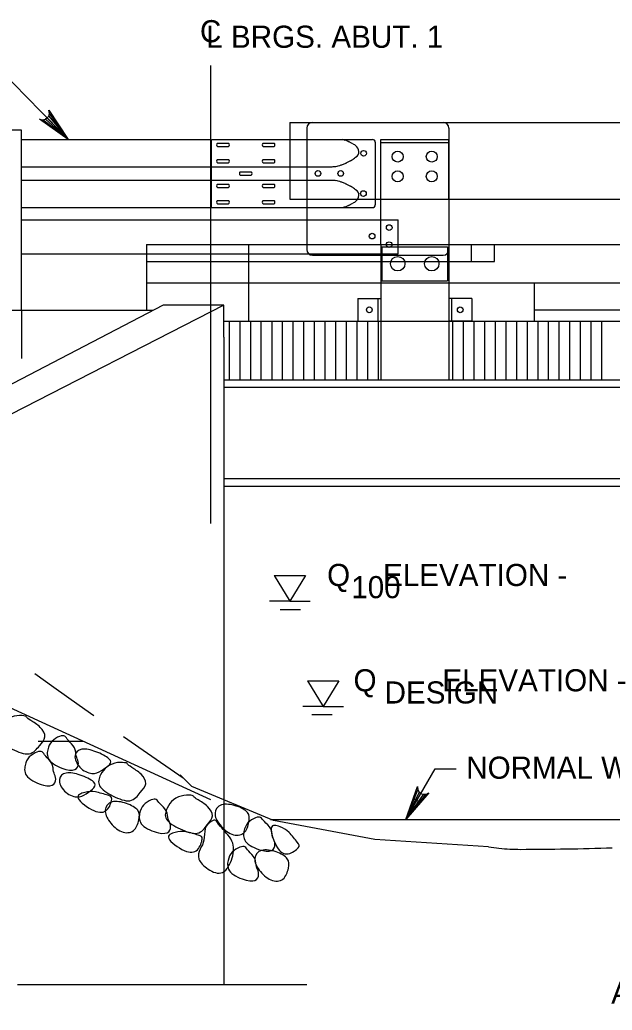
# Model space of a CAD drawing. Extents: x 638175 to 640495, y 294277 to 298435.
# Drawn here: x 638542.2 to 638622.4, y 297987.9 to 298122.2 of the extents above; entities that cross this region are included whole.
import ezdxf

# ---------------------------------------------------------------- set-up
doc = ezdxf.new("R2010")
doc.units = 0
for name, color, linetype in [('2', 7, 'Continuous'), ('3', 7, 'Continuous'), ('4', 7, 'Continuous'), ('5', 7, 'Continuous'), ('8', 7, 'Continuous'), ('Level 25', 7, 'Continuous')]:
    doc.layers.add(name, color=color, linetype=linetype)

msp = doc.modelspace()

# ---------------------------------------------------------------- linework, layer by layer
at = {"layer": '2'}
for p, q in [((638578.73, 298108.3), (638578.73, 298105.99)), ((638578.73, 298108.3), (638751.73, 298108.3)), ((638542.4, 298106), (638568.08, 298106)), ((638568.08, 298106), (638568.08, 298096.76)), ((638568.15, 298106), (638578.73, 298106)), ((638578.73, 298106), (638589.95, 298106)), ((638578.73, 298105.99), (638578.73, 298097.91)), ((638591.05, 298105.99), (638600.28, 298105.99)), ((638591.05, 298091.74), (638591.05, 298105.99)), ((638600.28, 298097.91), (638600.28, 298105.99)), ((638568.95, 298105.49), (638570.43, 298105.49)), ((638568.95, 298105.03), (638570.43, 298105.03)), ((638575.12, 298105.49), (638576.6, 298105.49)), ((638575.12, 298105.03), (638576.6, 298105.03)), ((638590.32, 298105.63), (638590.32, 298097.13)), ((638591.05, 298105.61), (638600.28, 298105.61)), ((638568.95, 298103.28), (638570.43, 298103.28)), ((638575.12, 298103.28), (638576.6, 298103.28)), ((638542.4, 298102.31), (638578.73, 298102.31)), ((638568.95, 298102.81), (638570.43, 298102.81)), ((638575.12, 298102.81), (638576.6, 298102.81)), ((638578.73, 298102.31), (638584.48, 298102.31)), ((638572.03, 298101.61), (638573.51, 298101.61)), ((638572.03, 298101.15), (638573.51, 298101.15)), ((638542.4, 298100.46), (638578.73, 298100.46)), ((638568.95, 298099.95), (638570.43, 298099.95)), ((638568.95, 298099.49), (638570.43, 298099.49)), ((638575.12, 298099.95), (638576.6, 298099.95)), ((638575.12, 298099.49), (638576.6, 298099.49)), ((638578.73, 298100.46), (638584.48, 298100.46)), ((638578.73, 298097.91), (638581.04, 298097.91)), ((638581.04, 298097.91), (638591.05, 298097.91)), ((638591.05, 298097.91), (638600.28, 298097.91)), ((638600.28, 298097.91), (638600.28, 298091.74)), ((638600.28, 298097.91), (638638.71, 298097.91)), ((638542.4, 298096.76), (638581.04, 298096.76)), ((638568.95, 298097.73), (638570.43, 298097.73)), ((638568.95, 298097.27), (638570.43, 298097.27)), ((638575.12, 298097.73), (638576.6, 298097.73)), ((638575.12, 298097.27), (638576.6, 298097.27)), ((638581.04, 298096.76), (638589.95, 298096.76)), ((638542.4, 298095.1), (638581.04, 298095.1)), ((638581.04, 298095.1), (638593.4, 298095.1)), ((638593.4, 298090.48), (638593.4, 298095.1)), ((638559.3, 298091.74), (638591.05, 298091.74)), ((638559.3, 298091.74), (638559.3, 298082.8)), ((638573.15, 298091.74), (638573.15, 298081.36)), ((638581.04, 298091.74), (638581.04, 298091.08)), ((638591.05, 298091.74), (638591.05, 298073.42)), ((638591.05, 298091.74), (638600.28, 298091.74)), ((638591.21, 298091.46), (638591.21, 298086.85)), ((638591.21, 298091.46), (638600.09, 298091.46)), ((638600.09, 298091.46), (638600.09, 298086.85)), ((638600.28, 298091.74), (638600.28, 298073.42)), ((638600.28, 298091.74), (638638.71, 298091.74)), ((638603.36, 298089.44), (638603.36, 298091.74)), ((638606.45, 298089.44), (638606.45, 298091.74)), ((638542.4, 298090.48), (638559.3, 298090.48)), ((638559.3, 298090.48), (638593.4, 298090.48)), ((638559.3, 298089.44), (638606.45, 298089.44)), ((638559.3, 298086.55), (638591.05, 298086.55)), ((638591.05, 298086.55), (638600.28, 298086.55)), ((638591.21, 298086.85), (638600.09, 298086.85)), ((638600.28, 298086.55), (638616.44, 298086.55)), ((638611.82, 298086.55), (638611.82, 298081.36)), ((638612.04, 298086.55), (638638.71, 298086.55)), ((638587.96, 298084.45), (638591.05, 298084.45)), ((638587.96, 298084.45), (638587.96, 298081.36)), ((638590.68, 298084.45), (638590.68, 298081.36)), ((638591.05, 298084.45), (638591.05, 298081.36)), ((638603.38, 298084.45), (638600.28, 298084.45)), ((638600.28, 298084.45), (638600.28, 298081.36)), ((638600.65, 298084.45), (638600.65, 298081.36)), ((638603.38, 298084.45), (638603.38, 298081.36)), ((638611.82, 298082.89), (638625.9, 298082.89)), ((638587.96, 298081.36), (638591.05, 298081.36)), ((638591.05, 298081.36), (638600.28, 298081.36)), ((638603.38, 298081.36), (638600.28, 298081.36)), ((638600.28, 298081.36), (638638.71, 298081.36))]:
    msp.add_line(p, q, dxfattribs=at)
for centre, radius in [((638588.74, 298104.12), 0.385), ((638593.36, 298103.68), 0.748), ((638597.97, 298103.68), 0.748), ((638582.55, 298101.39), 0.385), ((638585.63, 298101.39), 0.385), ((638593.36, 298100.99), 0.748), ((638597.97, 298100.99), 0.748), ((638588.71, 298098.67), 0.385), ((638592.2, 298094.05), 0.385), ((638589.89, 298092.89), 0.385), ((638592.2, 298091.74), 0.385), ((638593.36, 298089.15), 0.978), ((638597.97, 298089.15), 0.978), ((638589.51, 298082.9), 0.385), ((638601.82, 298082.9), 0.385)]:
    msp.add_circle(centre, radius, dxfattribs=at)
for centre, radius, start, end in [((638582.91, 298096.28), 10.17, 71.5066, 72.9766), ((638589.95, 298105.63), 0.369, 0, 90), ((638569.09, 298105.26), 0.269, 120.8559, 239.1441), ((638570.29, 298105.26), 0.269, 300.8559, 59.1441), ((638575.26, 298105.26), 0.269, 120.8559, 239.1441), ((638576.46, 298105.26), 0.269, 300.8559, 59.1441), ((638585.53, 298104.13), 1.88, 68.0907, 71.5066), ((638562.09, 298045.83), 64.73, 67.6851, 68.0907), ((638584.41, 298100.22), 5.93, 66.3453, 67.6851), ((638585.82, 298103.44), 2.42, 63.4251, 66.3453), ((638572.67, 298077.16), 31.8, 62.6202, 63.4251), ((638586.86, 298104.55), 0.955, 54.6771, 62.6202), ((638584.86, 298101.73), 4.42, 50.9849, 54.6771), ((638587.18, 298104.37), 0.916, 301.3851, 59.6468), ((638569.09, 298103.05), 0.269, 120.8559, 239.1441), ((638570.29, 298103.05), 0.269, 300.8559, 59.1441), ((638575.26, 298103.05), 0.269, 120.8559, 239.1441), ((638576.46, 298103.05), 0.269, 300.8559, 59.1441), ((638399.66, 298448.44), 392.83, 298.4725, 298.525), ((638586.74, 298104.25), 1.09, 298.525, 306.8818), ((638584.42, 298107.33), 4.94, 306.8818, 310.7993), ((638584.25, 298107.33), 5.03, 272.6429, 278.367), ((638584.67, 298104.49), 2.16, 278.367, 287.1115), ((638558.25, 298190.32), 91.96, 287.1115, 287.3611), ((638584.75, 298105.55), 3.14, 287.3611, 288.7111), ((638579.93, 298119.78), 18.18, 288.7111, 290.2329), ((638585.99, 298103.33), 0.644, 290.2329, 298.3215), ((638576.12, 298121.65), 21.45, 298.3215, 298.7501), ((638641.79, 298001.95), 115.08, 118.565, 118.7501), ((638647.18, 297992.04), 126.36, 118.4725, 118.565), ((638572.17, 298101.38), 0.269, 120.8559, 239.1441), ((638573.37, 298101.38), 0.269, 300.8559, 59.1441), ((638569.09, 298099.72), 0.269, 120.8559, 239.1441), ((638570.29, 298099.72), 0.269, 300.8559, 59.1441), ((638575.26, 298099.72), 0.269, 120.8559, 239.1441), ((638576.46, 298099.72), 0.269, 300.8559, 59.1441), ((638584.25, 298095.43), 5.03, 81.633, 87.3571), ((638584.67, 298098.28), 2.16, 72.8885, 81.633), ((638558.25, 298012.45), 91.96, 72.6389, 72.8885), ((638584.75, 298097.22), 3.14, 71.2889, 72.6389), ((638579.93, 298082.98), 18.18, 69.7671, 71.2889), ((638585.99, 298099.43), 0.644, 61.6785, 69.7671), ((638576.12, 298081.11), 21.45, 61.2499, 61.6785), ((638641.79, 298200.82), 115.08, 241.2499, 241.435), ((638647.18, 298210.72), 126.36, 241.435, 241.5275), ((638399.66, 297754.33), 392.83, 61.475, 61.5275), ((638586.74, 298098.52), 1.09, 53.1182, 61.475), ((638584.42, 298095.44), 4.94, 49.2007, 53.1182), ((638587.18, 298098.4), 0.916, 300.3532, 58.6149), ((638569.09, 298097.5), 0.269, 120.8559, 239.1441), ((638570.29, 298097.5), 0.269, 300.8559, 59.1441), ((638575.26, 298097.5), 0.269, 120.8559, 239.1441), ((638576.46, 298097.5), 0.269, 300.8559, 59.1441), ((638582.91, 298106.49), 10.17, 287.0234, 288.4934), ((638585.53, 298098.63), 1.88, 288.4934, 291.9093), ((638562.09, 298156.93), 64.73, 291.9093, 292.3149), ((638584.41, 298102.54), 5.93, 292.3149, 293.6547), ((638585.82, 298099.32), 2.42, 293.6547, 296.5749), ((638572.67, 298125.6), 31.8, 296.5749, 297.3798), ((638586.86, 298098.21), 0.955, 297.3798, 305.3229), ((638584.86, 298101.04), 4.42, 305.3229, 309.0151), ((638589.95, 298097.13), 0.369, 270, 0)]:
    msp.add_arc(centre, radius, start, end, dxfattribs=at)
at = {"layer": '3'}
for p, q in [((638542.4, 298107.27), (638538.07, 298107.27)), ((638542.4, 298082.8), (638542.4, 298107.27)), ((638561.58, 298083.52), (638496.45, 298049.64)), ((638569.79, 298083.52), (638503.58, 298049.64)), ((638569.79, 298083.52), (638503.58, 298049.64)), ((638569.79, 298083.52), (638561.58, 298083.52)), ((638569.79, 298083.52), (638561.58, 298083.52)), ((638569.79, 298079.19), (638569.79, 298083.52)), ((638569.79, 298079.19), (638569.79, 298083.52)), ((638560.19, 298082.8), (638486.79, 298082.8)), ((638560.19, 298082.8), (638495, 298082.8)), ((638542.4, 298082.8), (638542.4, 298076.31)), ((638569.79, 298081.36), (638591.05, 298081.36)), ((638569.79, 298079.19), (638569.79, 298016.47)), ((638569.79, 298073.43), (638748.57, 298073.43)), ((638569.79, 298073.43), (638748.57, 298073.43)), ((638569.79, 298073.42), (638748.57, 298073.42)), ((638569.79, 298072.43), (638748.57, 298072.43)), ((638569.79, 298060.01), (638748.57, 298060.01)), ((638569.79, 298059.01), (638748.57, 298059.01)), ((638526.61, 298035.47), (638567.99, 298016.49)), ((638544.63, 298024.41), (638550.73, 298024.41)), ((638569.79, 298016.47), (638569.79, 297991.42)), ((638576.14, 298013.81), (638736.87, 298013.81)), ((638541.85, 297991.42), (638581.05, 297991.42))]:
    msp.add_line(p, q, dxfattribs=at)
for centre, radius, start, end in [((638614.92, 298080.58), 71.1, 262.5202, 263.6598), ((638609.98, 298036.06), 26.31, 263.6598, 270.0618), ((638609.6, 298380.65), 370.9, 270.0618, 271.9788)]:
    msp.add_arc(centre, radius, start, end, dxfattribs=at)
for points in [[(638543.08, 298027.66), (638543.14, 298027.58), (638543.47, 298027.29), (638545.06, 298026.38), (638545.85, 298024.94), (638544.85, 298023.89), (638543.64, 298022.27), (638541.07, 298023.27), (638538.85, 298024.68), (638539.39, 298026.28), (638540.18, 298027.4), (638541.79, 298028.01), (638543.13, 298027.8), (638543.03, 298027.75), (638543.08, 298027.66)], [(638549.8, 298022.41), (638549.86, 298022.11), (638550.17, 298021.74), (638550.02, 298020.52), (638548.67, 298020.35), (638545.78, 298021.6), (638545.87, 298023.36), (638546.38, 298024.46), (638547.64, 298025.16), (638548.3, 298025.19), (638548.6, 298024.58), (638549.77, 298023.55), (638549.73, 298022.71), (638549.8, 298022.41)], [(638546.73, 298020.29), (638546.8, 298019.99), (638547.1, 298019.62), (638546.95, 298018.4), (638545.6, 298018.23), (638542.71, 298019.48), (638542.8, 298021.24), (638543.32, 298022.34), (638544.58, 298023.04), (638545.23, 298023.08), (638545.53, 298022.46), (638546.7, 298021.43), (638546.67, 298020.59), (638546.73, 298020.29)], [(638554.29, 298021.22), (638554.05, 298020.96), (638553.18, 298020.41), (638552.07, 298019.77), (638550.09, 298020.71), (638549.33, 298022.63), (638550.42, 298023.54), (638552.44, 298023.1), (638554.62, 298021.96), (638554.53, 298021.48), (638554.29, 298021.22)], [(638556.75, 298021.31), (638556.8, 298021.22), (638557.14, 298020.94), (638558.72, 298020.02), (638559.52, 298018.59), (638558.51, 298017.54), (638557.31, 298015.91), (638554.73, 298016.91), (638552.51, 298018.32), (638553.06, 298019.92), (638553.85, 298021.04), (638555.45, 298021.65), (638556.8, 298021.44), (638556.69, 298021.39), (638556.75, 298021.31)], [(638552.2, 298018.1), (638551.97, 298017.84), (638551.11, 298017.26), (638550.03, 298016.59), (638548.02, 298017.48), (638547.21, 298019.39), (638548.28, 298020.32), (638550.31, 298019.93), (638552.52, 298018.85), (638552.43, 298018.36), (638552.2, 298018.1)], [(638554.06, 298017.09), (638554.48, 298016.96), (638554.79, 298016.86), (638554.14, 298014.79), (638552.42, 298014.57), (638549.24, 298016.95), (638551.07, 298017.53), (638552.25, 298017.66), (638553.64, 298017.22), (638554.06, 298017.09)], [(638558.13, 298015.04), (638558.41, 298014.67), (638558.37, 298013.83), (638557.75, 298012.01), (638555.9, 298011.87), (638554.16, 298013.49), (638553.46, 298015.13), (638554.43, 298016.46), (638556.7, 298016.06), (638557.85, 298015.41), (638558.13, 298015.04)], [(638562.27, 298013.86), (638562.34, 298013.56), (638562.65, 298013.2), (638562.53, 298011.97), (638561.19, 298011.77), (638558.27, 298012.94), (638558.32, 298014.7), (638558.8, 298015.82), (638560.04, 298016.56), (638560.7, 298016.6), (638561.01, 298016), (638562.21, 298015), (638562.19, 298014.16), (638562.27, 298013.86)], [(638565.72, 298016.89), (638565.78, 298016.81), (638566.12, 298016.53), (638567.73, 298015.65), (638568.56, 298014.24), (638567.59, 298013.17), (638566.43, 298011.51), (638563.82, 298012.44), (638561.57, 298013.8), (638562.07, 298015.41), (638562.83, 298016.55), (638564.42, 298017.2), (638565.77, 298017.03), (638565.67, 298016.97), (638565.72, 298016.89)], [(638573.01, 298014.74), (638573.3, 298014.38), (638573.28, 298013.54), (638572.7, 298011.69), (638570.87, 298011.51), (638569.08, 298013.09), (638568.33, 298014.7), (638569.27, 298016.07), (638571.55, 298015.72), (638572.72, 298015.1), (638573.01, 298014.74)], [(638568.71, 298013.66), (638568.86, 298013.57), (638568.98, 298013.12), (638571.3, 298010.87), (638571.11, 298008.65), (638569.78, 298006.03), (638567.55, 298006.98), (638566.1, 298008.45), (638566.54, 298009.84), (638567.26, 298010.87), (638567.07, 298012.71), (638568.13, 298013.64), (638568.57, 298013.75), (638568.71, 298013.66)], [(638576.41, 298011.44), (638576.48, 298011.14), (638576.79, 298010.78), (638576.67, 298009.56), (638575.33, 298009.35), (638572.41, 298010.53), (638572.45, 298012.28), (638572.94, 298013.4), (638574.18, 298014.14), (638574.83, 298014.18), (638575.15, 298013.58), (638576.35, 298012.58), (638576.33, 298011.74), (638576.41, 298011.44)], [(638566.32, 298011.68), (638566.74, 298011.54), (638567.04, 298011.45), (638566.39, 298009.38), (638564.68, 298009.16), (638561.49, 298011.54), (638563.32, 298012.11), (638564.51, 298012.25), (638565.89, 298011.81), (638566.32, 298011.68)], [(638579.74, 298010.72), (638580.01, 298010.37), (638580.21, 298010.12), (638578.48, 298008.79), (638576.95, 298009.59), (638575.71, 298013.37), (638577.54, 298012.8), (638578.58, 298012.23), (638579.47, 298011.07), (638579.74, 298010.72)], [(638574.22, 298007.39), (638574.29, 298007.09), (638574.59, 298006.73), (638574.44, 298005.5), (638573.1, 298005.33), (638570.2, 298006.58), (638570.3, 298008.34), (638570.81, 298009.44), (638572.07, 298010.15), (638572.72, 298010.18), (638573.02, 298009.57), (638574.19, 298008.53), (638574.16, 298007.69), (638574.22, 298007.39)], [(638578.4, 298008.48), (638578.68, 298008.11), (638578.64, 298007.27), (638578.01, 298005.44), (638576.17, 298005.31), (638574.42, 298006.93), (638573.72, 298008.56), (638574.69, 298009.9), (638576.97, 298009.49), (638578.12, 298008.85), (638578.4, 298008.48)]]:
    msp.add_open_spline(points, degree=3, dxfattribs=at)
at = {"layer": '4'}
for p, q in [((638548.7, 298106), (638539.42, 298115.47)), ((638567.99, 298116.03), (638567.99, 298053.94)), ((638576.62, 298046.89), (638578.74, 298043.41)), ((638576.62, 298046.89), (638580.86, 298046.89)), ((638580.86, 298046.89), (638578.74, 298043.41)), ((638578.74, 298043.41), (638575.97, 298043.41)), ((638578.74, 298043.41), (638581.51, 298043.41)), ((638577.43, 298042.26), (638580.2, 298042.26)), ((638581.14, 298032.61), (638585.38, 298032.61)), ((638581.14, 298032.61), (638583.26, 298029.13)), ((638585.38, 298032.61), (638583.26, 298029.13)), ((638583.26, 298029.13), (638580.49, 298029.13)), ((638583.26, 298029.13), (638586.03, 298029.13)), ((638581.71, 298028.04), (638584.48, 298028.04)), ((638594.44, 298013.81), (638598.45, 298020.66)), ((638598.45, 298020.66), (638601.26, 298020.66))]:
    msp.add_line(p, q, dxfattribs=at)
for points in [[(638548.7, 298106), (638544.84, 298108.75), (638545.27, 298108.66), (638545.62, 298108.75), (638545.88, 298108.92), (638546.07, 298109.18), (638546.17, 298109.53), (638546.1, 298109.96), (638548.7, 298106), (638546.17, 298109.53), (638546.07, 298109.18), (638548.7, 298106), (638545.88, 298108.92), (638545.62, 298108.75), (638548.7, 298106), (638545.27, 298108.66)], [(638605.67, 298010.08), (638590.26, 298011.08), (638576.51, 298013.65), (638565.47, 298018.27), (638563.9, 298019.83)], [(638594.44, 298013.81), (638596.04, 298018.27), (638596.07, 298017.83), (638596.25, 298017.52), (638596.49, 298017.31), (638596.79, 298017.2), (638597.15, 298017.2), (638597.55, 298017.39), (638594.44, 298013.81), (638597.15, 298017.2), (638596.79, 298017.2), (638594.44, 298013.81), (638596.49, 298017.31), (638596.25, 298017.52), (638594.44, 298013.81), (638596.07, 298017.83)]]:
    msp.add_lwpolyline(points, dxfattribs=at)
msp.add_lwpolyline([(638595.55, 298016.65), (638596.38, 298016.16), (638594.5, 298013.92)], close=True, dxfattribs=at)
at = {"layer": '5'}
for p, q in [((638570.51, 298081.36), (638570.51, 298073.43)), ((638570.51, 298081.36), (638570.51, 298073.42)), ((638571.95, 298081.36), (638571.95, 298073.43)), ((638571.95, 298081.36), (638571.95, 298073.42)), ((638573.39, 298081.36), (638573.39, 298073.43)), ((638573.39, 298081.36), (638573.39, 298073.42)), ((638574.83, 298081.36), (638574.83, 298073.43)), ((638574.83, 298081.36), (638574.83, 298073.42)), ((638576.28, 298081.36), (638576.28, 298073.43)), ((638576.28, 298081.36), (638576.28, 298073.42)), ((638577.72, 298081.36), (638577.72, 298073.43)), ((638577.72, 298081.36), (638577.72, 298073.42)), ((638579.16, 298081.36), (638579.16, 298073.43)), ((638579.16, 298081.36), (638579.16, 298073.42)), ((638580.6, 298081.36), (638580.6, 298073.43)), ((638580.6, 298081.36), (638580.6, 298073.42)), ((638582.04, 298081.36), (638582.04, 298073.43)), ((638582.04, 298081.36), (638582.04, 298073.42)), ((638583.48, 298081.36), (638583.48, 298073.42)), ((638584.93, 298081.36), (638584.93, 298073.42)), ((638586.37, 298081.36), (638586.37, 298073.42)), ((638587.81, 298081.36), (638587.81, 298073.42)), ((638589.25, 298081.36), (638589.25, 298073.42)), ((638590.69, 298081.36), (638590.69, 298073.42)), ((638600.79, 298081.36), (638600.79, 298073.43)), ((638600.79, 298081.36), (638600.79, 298073.42)), ((638602.23, 298081.36), (638602.23, 298073.43)), ((638602.23, 298081.36), (638602.23, 298073.42)), ((638603.67, 298081.36), (638603.67, 298073.43)), ((638603.67, 298081.36), (638603.67, 298073.42)), ((638605.11, 298081.36), (638605.11, 298073.43)), ((638605.11, 298081.36), (638605.11, 298073.42)), ((638606.55, 298081.36), (638606.55, 298073.43)), ((638606.55, 298081.36), (638606.55, 298073.42)), ((638607.99, 298081.36), (638607.99, 298073.43)), ((638607.99, 298081.36), (638607.99, 298073.42)), ((638609.44, 298081.36), (638609.44, 298073.43)), ((638609.44, 298081.36), (638609.44, 298073.42)), ((638610.88, 298081.36), (638610.88, 298073.43)), ((638610.88, 298081.36), (638610.88, 298073.42)), ((638612.32, 298081.36), (638612.32, 298073.43)), ((638612.32, 298081.36), (638612.32, 298073.42)), ((638613.76, 298081.36), (638613.76, 298073.43)), ((638613.76, 298081.36), (638613.76, 298073.42)), ((638615.2, 298081.36), (638615.2, 298073.43)), ((638615.2, 298081.36), (638615.2, 298073.42)), ((638616.65, 298081.36), (638616.65, 298073.43)), ((638616.65, 298081.36), (638616.65, 298073.42)), ((638618.09, 298081.36), (638618.09, 298073.43)), ((638618.09, 298081.36), (638618.09, 298073.42)), ((638619.53, 298081.36), (638619.53, 298073.43)), ((638619.53, 298081.36), (638619.53, 298073.42)), ((638620.97, 298081.36), (638620.97, 298073.43)), ((638620.97, 298081.36), (638620.97, 298073.42))]:
    msp.add_line(p, q, dxfattribs=at)
at = {"layer": '8'}
for p, q in [((638546.77, 298031.69), (638544.17, 298033.54)), ((638550.19, 298029.25), (638546.77, 298031.69)), ((638552.19, 298027.84), (638550.19, 298029.25)), ((638558.86, 298023.17), (638556.22, 298025.01)), ((638564.31, 298019.42), (638558.86, 298023.17))]:
    msp.add_line(p, q, dxfattribs=at)
at = {"layer": 'Level 25'}
for p, q in [((638581.04, 298107.53), (638581.04, 298105.99)), ((638581.81, 298108.3), (638599.51, 298108.3)), ((638600.28, 298107.53), (638600.28, 298105.99)), ((638581.04, 298105.99), (638581.04, 298096.76)), ((638600.28, 298105.99), (638600.28, 298091.08)), ((638581.04, 298096.76), (638581.04, 298091.74)), ((638581.81, 298090.31), (638599.51, 298090.31))]:
    msp.add_line(p, q, dxfattribs=at)
for centre, start, end in [((638581.81, 298107.53), 90, 180), ((638599.51, 298107.53), 0, 90), ((638581.81, 298091.08), 180, 270), ((638599.51, 298091.08), 270, 0)]:
    msp.add_arc(centre, 0.77, start, end, dxfattribs=at)

# ---------------------------------------------------------------- texts
at = {"layer": '4'}
for s, p in [('C', (638566.56, 298119.18)), ('L BRGS. ABUT. 1', (638567.42, 298118.43)), ('Q    ELEVATION - ', (638583.79, 298045.45)), ('100', (638587.06, 298043.8)), ('Q        ELEVATION - ', (638587.37, 298031.17)), ('DESIGN', (638591.58, 298029.52)), ('NORMAL WATER ELEV. -', (638602.64, 298019.32)), ('AS PER DESIGN (MIN. R-6)', (638622.29, 297988.84))]:
    msp.add_text(s, height=3, dxfattribs=at).set_placement(p)

doc.saveas('drawing.dxf')
